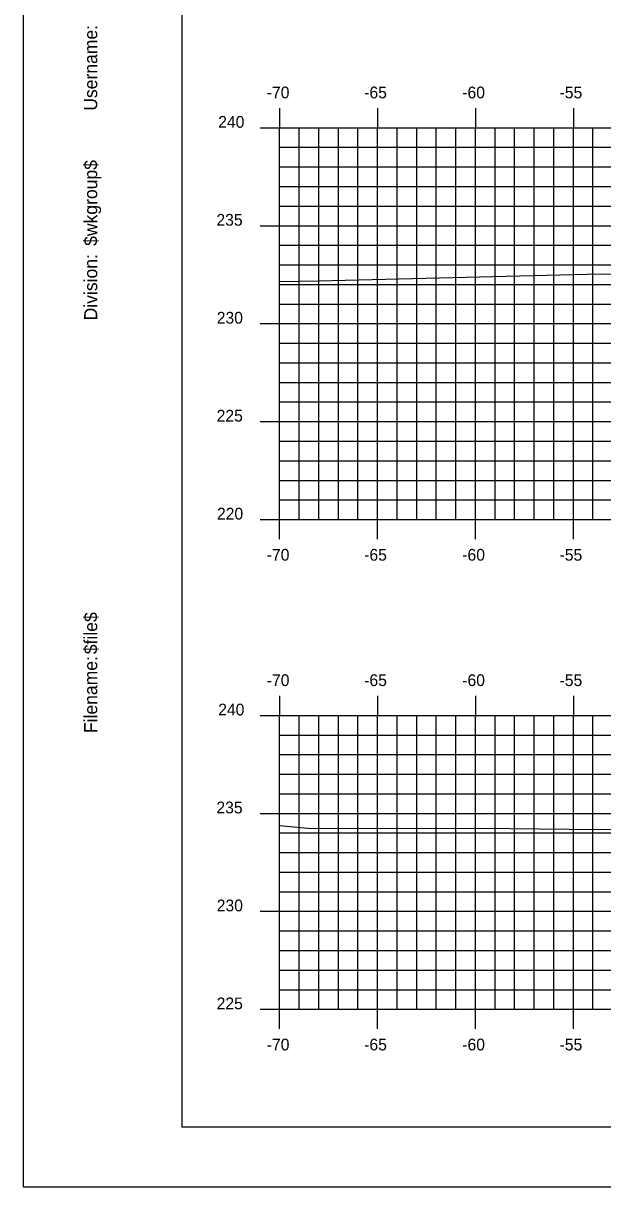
# Model space of a CAD drawing. Extents: x 1136767 to 1136937, y 608981 to 609091.
# Drawn here: x 1136767.3 to 1136796.9, y 608981.3 to 609040.7 of the extents above; entities that cross this region are included whole.
import ezdxf

# ---------------------------------------------------------------- set-up
doc = ezdxf.new("R2010")
doc.units = 0
for name, color, linetype in [('BORDER', 7, 'Continuous'), ('H_V ANNOTATION', 7, 'Continuous'), ('MAJOR', 7, 'Continuous'), ('MINOR', 7, 'Continuous'), ('PLOT BOUNDARY', 7, 'Continuous'), ('S_Roadway_Centerline', 7, 'Continuous')]:
    doc.layers.add(name, color=color, linetype=linetype)

msp = doc.modelspace()

# ---------------------------------------------------------------- linework, layer by layer
at = {"layer": 'BORDER'}
msp.add_lwpolyline([(1136775.383, 608984.335), (1136935.383, 608984.335), (1136935.383, 609089.335), (1136775.383, 609089.335)], close=True, dxfattribs=at)
at = {"layer": 'MAJOR'}
for p, q in [((1136780.383, 609036.337), (1136780.383, 609035.335)), ((1136785.383, 609036.337), (1136785.383, 609035.335)), ((1136790.383, 609036.337), (1136790.383, 609035.335)), ((1136795.383, 609036.337), (1136795.383, 609035.335)), ((1136779.381, 609035.335), (1136780.383, 609035.335)), ((1136780.383, 609035.335), (1136920.383, 609035.335)), ((1136780.383, 609015.335), (1136780.383, 609035.335)), ((1136780.383, 609015.335), (1136780.383, 609035.335)), ((1136780.383, 609035.335), (1136920.383, 609035.335)), ((1136785.383, 609015.335), (1136785.383, 609035.335)), ((1136790.383, 609015.335), (1136790.383, 609035.335)), ((1136795.383, 609015.335), (1136795.383, 609035.335)), ((1136779.381, 609030.335), (1136780.383, 609030.335)), ((1136780.383, 609030.335), (1136920.383, 609030.335)), ((1136779.381, 609025.335), (1136780.383, 609025.335)), ((1136780.383, 609025.335), (1136920.383, 609025.335)), ((1136779.381, 609020.335), (1136780.383, 609020.335)), ((1136780.383, 609020.335), (1136920.383, 609020.335)), ((1136779.381, 609015.335), (1136780.383, 609015.335)), ((1136780.383, 609015.335), (1136920.383, 609015.335)), ((1136780.383, 609015.335), (1136920.383, 609015.335)), ((1136780.383, 609014.333), (1136780.383, 609015.335)), ((1136785.383, 609014.333), (1136785.383, 609015.335)), ((1136790.383, 609014.333), (1136790.383, 609015.335)), ((1136795.383, 609014.333), (1136795.383, 609015.335)), ((1136780.383, 609006.337), (1136780.383, 609005.335)), ((1136785.383, 609006.337), (1136785.383, 609005.335)), ((1136790.383, 609006.337), (1136790.383, 609005.335)), ((1136795.383, 609006.337), (1136795.383, 609005.335)), ((1136779.381, 609005.335), (1136780.383, 609005.335)), ((1136780.383, 609005.335), (1136920.383, 609005.335)), ((1136780.383, 608990.335), (1136780.383, 609005.335)), ((1136780.383, 608990.335), (1136780.383, 609005.335)), ((1136780.383, 609005.335), (1136920.383, 609005.335)), ((1136785.383, 608990.335), (1136785.383, 609005.335)), ((1136790.383, 608990.335), (1136790.383, 609005.335)), ((1136795.383, 608990.335), (1136795.383, 609005.335)), ((1136779.381, 609000.335), (1136780.383, 609000.335)), ((1136780.383, 609000.335), (1136920.383, 609000.335)), ((1136779.381, 608995.335), (1136780.383, 608995.335)), ((1136780.383, 608995.335), (1136920.383, 608995.335)), ((1136779.381, 608990.335), (1136780.383, 608990.335)), ((1136780.383, 608990.335), (1136920.383, 608990.335)), ((1136780.383, 608990.335), (1136920.383, 608990.335)), ((1136780.383, 608989.333), (1136780.383, 608990.335)), ((1136785.383, 608989.333), (1136785.383, 608990.335)), ((1136790.383, 608989.333), (1136790.383, 608990.335)), ((1136795.383, 608989.333), (1136795.383, 608990.335))]:
    msp.add_line(p, q, dxfattribs=at)
at = {"layer": 'MINOR'}
for p, q in [((1136781.383, 609015.335), (1136781.383, 609035.335)), ((1136782.383, 609015.335), (1136782.383, 609035.335)), ((1136783.383, 609015.335), (1136783.383, 609035.335)), ((1136784.383, 609015.335), (1136784.383, 609035.335)), ((1136786.383, 609015.335), (1136786.383, 609035.335)), ((1136787.383, 609015.335), (1136787.383, 609035.335)), ((1136788.383, 609015.335), (1136788.383, 609035.335)), ((1136789.383, 609015.335), (1136789.383, 609035.335)), ((1136791.383, 609015.335), (1136791.383, 609035.335)), ((1136792.383, 609015.335), (1136792.383, 609035.335)), ((1136793.383, 609015.335), (1136793.383, 609035.335)), ((1136794.383, 609015.335), (1136794.383, 609035.335)), ((1136796.383, 609015.335), (1136796.383, 609035.335)), ((1136780.383, 609034.335), (1136920.383, 609034.335)), ((1136780.383, 609034.335), (1136781.385, 609034.335)), ((1136780.383, 609033.335), (1136920.383, 609033.335)), ((1136780.383, 609033.335), (1136781.385, 609033.335)), ((1136780.383, 609032.335), (1136920.383, 609032.335)), ((1136780.383, 609032.335), (1136781.385, 609032.335)), ((1136780.383, 609031.335), (1136920.383, 609031.335)), ((1136780.383, 609031.335), (1136781.385, 609031.335)), ((1136780.383, 609029.335), (1136920.383, 609029.335)), ((1136780.383, 609029.335), (1136781.385, 609029.335)), ((1136780.383, 609028.335), (1136920.383, 609028.335)), ((1136780.383, 609028.335), (1136781.385, 609028.335)), ((1136780.383, 609027.335), (1136920.383, 609027.335)), ((1136780.383, 609027.335), (1136781.385, 609027.335)), ((1136780.383, 609026.335), (1136920.383, 609026.335)), ((1136780.383, 609026.335), (1136781.385, 609026.335)), ((1136780.383, 609024.335), (1136920.383, 609024.335)), ((1136780.383, 609024.335), (1136781.385, 609024.335)), ((1136780.383, 609023.335), (1136920.383, 609023.335)), ((1136780.383, 609023.335), (1136781.385, 609023.335)), ((1136780.383, 609022.335), (1136920.383, 609022.335)), ((1136780.383, 609022.335), (1136781.385, 609022.335)), ((1136780.383, 609021.335), (1136920.383, 609021.335)), ((1136780.383, 609021.335), (1136781.385, 609021.335)), ((1136780.383, 609019.335), (1136920.383, 609019.335)), ((1136780.383, 609019.335), (1136781.385, 609019.335)), ((1136780.383, 609018.335), (1136920.383, 609018.335)), ((1136780.383, 609018.335), (1136781.385, 609018.335)), ((1136780.383, 609017.335), (1136920.383, 609017.335)), ((1136780.383, 609017.335), (1136781.385, 609017.335)), ((1136780.383, 609016.335), (1136920.383, 609016.335)), ((1136780.383, 609016.335), (1136781.385, 609016.335)), ((1136781.383, 608990.335), (1136781.383, 609005.335)), ((1136782.383, 608990.335), (1136782.383, 609005.335)), ((1136783.383, 608990.335), (1136783.383, 609005.335)), ((1136784.383, 608990.335), (1136784.383, 609005.335)), ((1136786.383, 608990.335), (1136786.383, 609005.335)), ((1136787.383, 608990.335), (1136787.383, 609005.335)), ((1136788.383, 608990.335), (1136788.383, 609005.335)), ((1136789.383, 608990.335), (1136789.383, 609005.335)), ((1136791.383, 608990.335), (1136791.383, 609005.335)), ((1136792.383, 608990.335), (1136792.383, 609005.335)), ((1136793.383, 608990.335), (1136793.383, 609005.335)), ((1136794.383, 608990.335), (1136794.383, 609005.335)), ((1136796.383, 608990.335), (1136796.383, 609005.335)), ((1136780.383, 609004.335), (1136920.383, 609004.335)), ((1136780.383, 609004.335), (1136781.385, 609004.335)), ((1136780.383, 609003.335), (1136920.383, 609003.335)), ((1136780.383, 609003.335), (1136781.385, 609003.335)), ((1136780.383, 609002.335), (1136920.383, 609002.335)), ((1136780.383, 609002.335), (1136781.385, 609002.335)), ((1136780.383, 609001.335), (1136920.383, 609001.335)), ((1136780.383, 609001.335), (1136781.385, 609001.335)), ((1136780.383, 608999.335), (1136920.383, 608999.335)), ((1136780.383, 608999.335), (1136781.385, 608999.335)), ((1136780.383, 608998.335), (1136920.383, 608998.335)), ((1136780.383, 608998.335), (1136781.385, 608998.335)), ((1136780.383, 608997.335), (1136920.383, 608997.335)), ((1136780.383, 608997.335), (1136781.385, 608997.335)), ((1136780.383, 608996.335), (1136920.383, 608996.335)), ((1136780.383, 608996.335), (1136781.385, 608996.335)), ((1136780.383, 608994.335), (1136920.383, 608994.335)), ((1136780.383, 608994.335), (1136781.385, 608994.335)), ((1136780.383, 608993.335), (1136920.383, 608993.335)), ((1136780.383, 608993.335), (1136781.385, 608993.335)), ((1136780.383, 608992.335), (1136920.383, 608992.335)), ((1136780.383, 608992.335), (1136781.385, 608992.335)), ((1136780.383, 608991.335), (1136920.383, 608991.335)), ((1136780.383, 608991.335), (1136781.385, 608991.335))]:
    msp.add_line(p, q, dxfattribs=at)
at = {"layer": 'PLOT BOUNDARY'}
msp.add_lwpolyline([(1136767.29, 608981.276), (1136937.29, 608981.276), (1136937.29, 609091.276), (1136767.29, 609091.276)], close=True, dxfattribs=at)
at = {"layer": 'S_Roadway_Centerline'}
for points in [[(1136780.383, 609027.49), (1136782.368, 609027.522), (1136796.751, 609027.884), (1136802.122, 609027.834), (1136803.598, 609027.827), (1136818.354, 609027.839), (1136822.194, 609027.792), (1136827.669, 609027.966)], [(1136780.383, 608999.708), (1136782.016, 608999.564), (1136790.64, 608999.588), (1136795.162, 608999.534), (1136805.193, 608999.485), (1136810.391, 608999.336), (1136814.548, 608999.253), (1136819.07, 608999.229), (1136827.733, 608999.346)]]:
    msp.add_lwpolyline(points, dxfattribs=at)

# ---------------------------------------------------------------- texts
at = {"layer": 'BORDER'}
for s, p in [('Username:', (1136771.068, 609036.203)), ('$wkgroup$', (1136771.068, 609029.305)), ('Division:', (1136771.068, 609025.501)), ('$file$', (1136771.068, 609008.461)), ('Filename:', (1136771.068, 609004.433))]:
    msp.add_text(s, height=0.6696, rotation=90, dxfattribs=at).set_placement(p)
at = {"layer": 'H_V ANNOTATION'}
for s, p in [('-70', (1136779.725, 609036.835)), ('-65', (1136784.701, 609036.835)), ('-60', (1136789.709, 609036.835)), ('-55', (1136794.679, 609036.835)), ('240', (1136777.245, 609035.335)), ('235', (1136777.154, 609030.335)), ('230', (1136777.17, 609025.335)), ('225', (1136777.165, 609020.335)), ('220', (1136777.181, 609015.335)), ('-70', (1136779.725, 609013.235)), ('-65', (1136784.701, 609013.235)), ('-60', (1136789.709, 609013.235)), ('-55', (1136794.679, 609013.235)), ('-70', (1136779.725, 609006.835)), ('-65', (1136784.701, 609006.835)), ('-60', (1136789.709, 609006.835)), ('-55', (1136794.679, 609006.835)), ('240', (1136777.245, 609005.335)), ('235', (1136777.154, 609000.335)), ('230', (1136777.17, 608995.335)), ('225', (1136777.165, 608990.335)), ('-70', (1136779.725, 608988.235)), ('-65', (1136784.701, 608988.235)), ('-60', (1136789.709, 608988.235)), ('-55', (1136794.679, 608988.235))]:
    msp.add_text(s, height=0.6, dxfattribs=at).set_placement(p)
at = {"layer": 'MAJOR'}
for p in [(1136780.379, 609015.335), (1136780.379, 608990.335)]:
    msp.add_text('-', height=0.006, dxfattribs=at).set_placement(p)

doc.saveas('drawing.dxf')
